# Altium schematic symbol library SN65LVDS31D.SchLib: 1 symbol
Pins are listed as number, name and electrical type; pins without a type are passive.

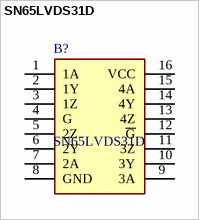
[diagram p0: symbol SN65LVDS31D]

## SN65LVDS31D
designator B?
SN65LVDS31D, LVDS Transmitter Quad LVTTL 400Mbit/s, 3  3.6 V, 16-Pin, SOIC; Manufacturer_Name: Texas Instruments; Geometry.Height: 1.75mm
footprint SOIC127P600X175-16N
pins: 1 1A, 2 1Y, 3 1Z, 4 G, 5 2Z, 6 2Y, 7 2A, 8 GND, 9 3A, 10 3Y, 11 3Z, 12 ~{G}, 13 4Z, 14 4Y, 15 4A, 16 VCC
